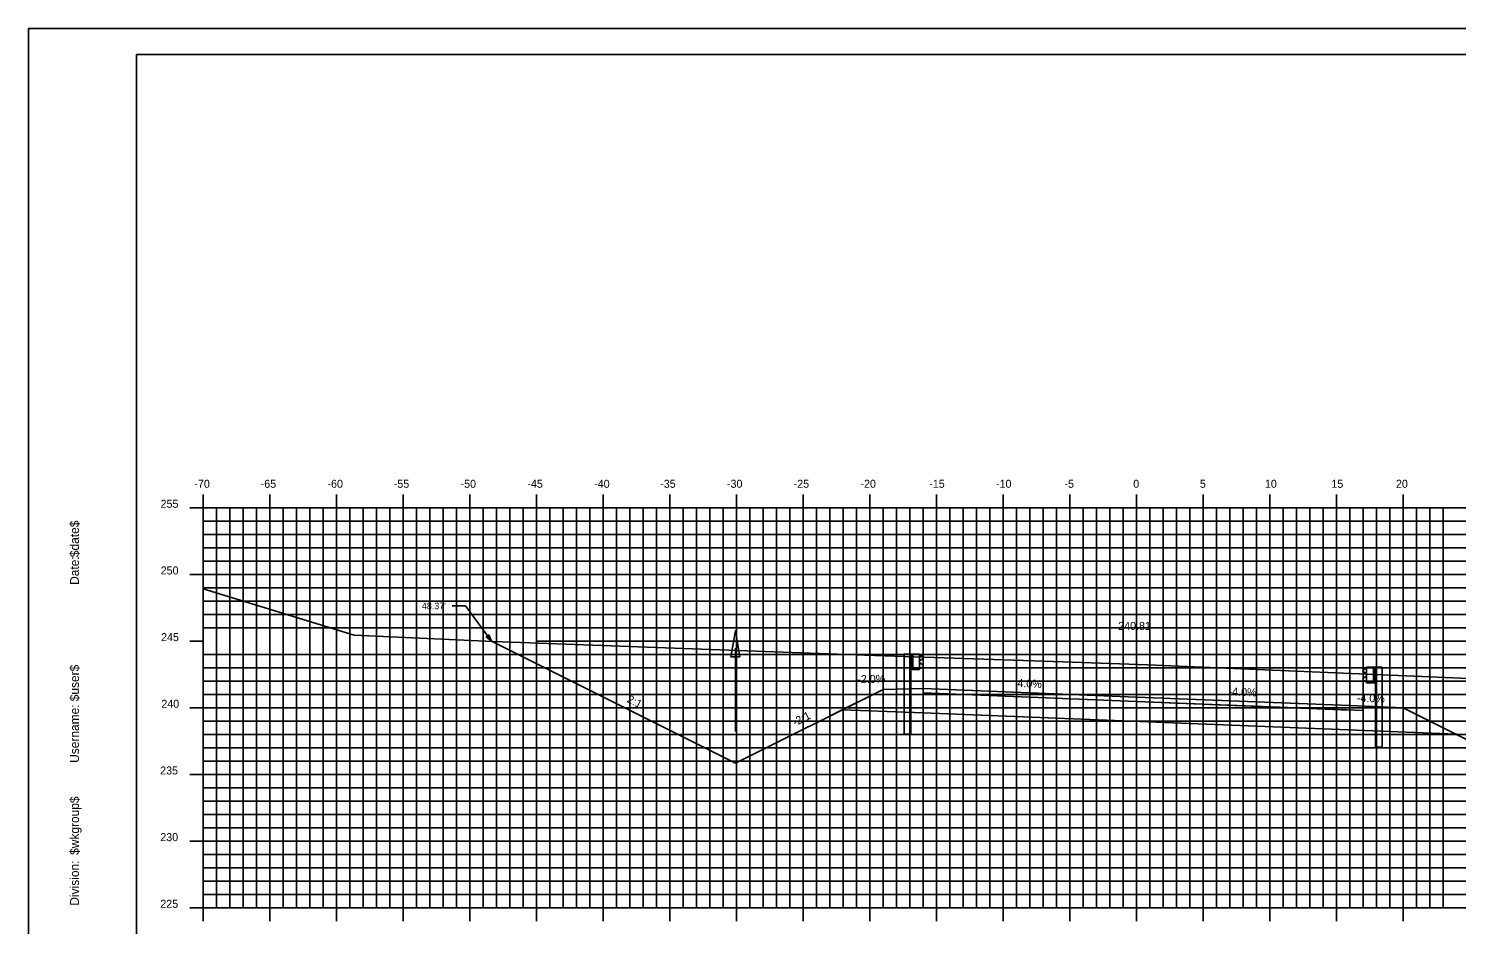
# Model space of a CAD drawing. Extents: x 1160718 to 1173142, y 616002 to 617630.
# Drawn here: x 1168548.8 to 1168655.8, y 616656.7 to 616723.9 of the extents above; entities that cross this region are included whole.
import ezdxf

# ---------------------------------------------------------------- set-up
doc = ezdxf.new("R2010")
doc.units = 0
for name, color, linetype in [('ANNOTATION', 7, 'Continuous'), ('BORDER', 7, 'Continuous'), ('D_Drainage_Ditch_Line', 7, 'Continuous'), ('D_Guardrail_Beam_Lt', 7, 'Continuous'), ('D_Guardrail_Beam_Rt', 7, 'Continuous'), ('D_Roadway_Centerline', 7, 'Continuous'), ('D_Roadway_Centerline_Text', 7, 'Continuous'), ('D_Roadway_Edge_Shoulder', 7, 'Continuous'), ('D_Roadway_Edge_TW', 7, 'Continuous'), ('D_Roadway_Pavement', 7, 'Continuous'), ('D_Roadway_SlopeLines', 7, 'Continuous'), ('D_Roadway_SubGrade', 7, 'Continuous'), ('H_V ANNOTATION', 7, 'Continuous'), ('MAJOR', 7, 'Continuous'), ('MINOR', 7, 'Continuous'), ('PLOT BOUNDARY', 7, 'Continuous'), ('S_Roadway_Centerline', 7, 'Continuous'), ('SHADING', 7, 'Continuous')]:
    doc.layers.add(name, color=color, linetype=linetype)

msp = doc.modelspace()

# ---------------------------------------------------------------- linework, layer by layer
at = {"layer": 'ANNOTATION'}
for p, q in [((1168580.52, 616680.57), (1168581.52, 616680.57)), ((1168583.49, 616677.92), (1168581.52, 616680.57)), ((1168647.85, 616673.09), (1168651.85, 616672.93))]:
    msp.add_line(p, q, dxfattribs=at)
msp.add_lwpolyline([(1168583.29, 616678.39), (1168583.49, 616677.92), (1168583.09, 616678.24)], close=True, dxfattribs=at)
at = {"layer": 'BORDER'}
for p, q in [((1168716.85, 616721.93), (1168556.85, 616721.93)), ((1168556.85, 616721.93), (1168556.85, 616616.93))]:
    msp.add_line(p, q, dxfattribs=at)
at = {"layer": 'D_Drainage_Ditch_Line'}
msp.add_line((1168601.77, 616677.39), (1168601.77, 616671.15), dxfattribs=at)
msp.add_lwpolyline([(1168602.1, 616676.74), (1168601.44, 616676.74), (1168601.77, 616678.71)], close=True, dxfattribs=at)
at = {"layer": 'D_Guardrail_Beam_Lt'}
for p, q in [((1168614.43, 616676.96), (1168614.43, 616670.96)), ((1168614.9, 616676.96), (1168614.43, 616676.96)), ((1168615.59, 616676.96), (1168614.9, 616676.96)), ((1168614.9, 616676.96), (1168614.9, 616675.79)), ((1168614.96, 616676.96), (1168614.96, 616675.79)), ((1168615.07, 616676.96), (1168615.07, 616675.79)), ((1168615.59, 616675.79), (1168615.59, 616676.96)), ((1168615.59, 616676.87), (1168615.66, 616676.86)), ((1168615.82, 616676.61), (1168615.63, 616676.47)), ((1168615.68, 616676.85), (1168615.82, 616676.75)), ((1168614.9, 616675.79), (1168615.59, 616675.79)), ((1168614.92, 616670.96), (1168614.92, 616675.79)), ((1168615.59, 616676.41), (1168615.59, 616676.34)), ((1168615.66, 616675.89), (1168615.59, 616675.87)), ((1168615.63, 616676.27), (1168615.82, 616676.14)), ((1168615.82, 616675.99), (1168615.68, 616675.89)), ((1168614.92, 616670.96), (1168614.43, 616670.96))]:
    msp.add_line(p, q, dxfattribs=at)
for centre, major_axis, start_param, end_param in [((1168615.67, 616676.41), (-0.0789, 0), 5.323254, 6.283185), ((1168615.65, 616676.82), (0.0417, 0), 0.959931, 1.376053), ((1168615.77, 616676.68), (0.0877, 0), 5.323254, 7.243116), ((1168615.67, 616676.34), (-0.0789, 0), 6.283185, 7.243116), ((1168615.65, 616675.93), (0.0417, 0), 4.907132, 5.323254), ((1168615.77, 616676.07), (0.0877, 0), 5.323254, 7.243116)]:
    msp.add_ellipse(centre, major_axis=major_axis, ratio=0.995501, start_param=start_param, end_param=end_param, dxfattribs=at)
at = {"layer": 'D_Guardrail_Beam_Rt'}
for p, q in [((1168649.02, 616675.87), (1168648.87, 616675.77)), ((1168648.87, 616675.63), (1168649.07, 616675.49)), ((1168649.11, 616675.89), (1168649.03, 616675.87)), ((1168649.1, 616675.42), (1168649.1, 616675.35)), ((1168649.11, 616675.97), (1168649.8, 616675.97)), ((1168649.11, 616674.81), (1168649.11, 616675.97)), ((1168649.63, 616675.97), (1168649.63, 616674.81)), ((1168649.73, 616675.97), (1168649.73, 616674.81)), ((1168649.8, 616675.97), (1168650.27, 616675.97)), ((1168649.8, 616675.97), (1168649.8, 616674.81)), ((1168650.27, 616675.97), (1168650.27, 616669.97)), ((1168649.07, 616675.29), (1168648.87, 616675.15)), ((1168648.87, 616675.01), (1168649.02, 616674.91)), ((1168649.03, 616674.9), (1168649.11, 616674.89)), ((1168649.8, 616674.81), (1168649.11, 616674.81)), ((1168649.77, 616669.97), (1168649.77, 616674.81)), ((1168649.77, 616669.97), (1168650.27, 616669.97))]:
    msp.add_line(p, q, dxfattribs=at)
for centre, major_axis, start_param, end_param in [((1168648.92, 616675.7), (-0.0877, 0), 5.323254, 7.243116), ((1168649.04, 616675.83), (-0.0417, 0), 4.907132, 5.323254), ((1168649.02, 616675.42), (0.0789, 0), 0, 0.959931), ((1168648.92, 616675.08), (-0.0877, 0), 5.323254, 7.243116), ((1168649.04, 616674.94), (-0.0417, 0), 0.959931, 1.376053), ((1168649.02, 616675.35), (0.0789, 0), 5.323254, 6.283185)]:
    msp.add_ellipse(centre, major_axis=major_axis, ratio=0.995501, start_param=start_param, end_param=end_param, dxfattribs=at)
at = {"layer": 'D_Roadway_Edge_Shoulder'}
msp.add_lwpolyline([(1168615.85, 616674.37), (1168615.85, 616674.04)], dxfattribs=at)
at = {"layer": 'D_Roadway_Edge_TW'}
for p, q in [((1168615.85, 616674.04), (1168615.85, 616674.37)), ((1168615.85, 616674.37), (1168631.85, 616673.73)), ((1168631.85, 616673.4), (1168615.85, 616674.04)), ((1168631.85, 616673.73), (1168647.85, 616673.09)), ((1168648.85, 616672.72), (1168631.85, 616673.4))]:
    msp.add_line(p, q, dxfattribs=at)
at = {"layer": 'D_Roadway_Pavement'}
msp.add_lwpolyline([(1168615.85, 616674.04), (1168615.85, 616674.04), (1168631.85, 616673.4), (1168647.85, 616672.76), (1168647.85, 616672.76), (1168631.85, 616673.4)], close=True, dxfattribs=at)
for points in [[(1168615.85, 616674.04), (1168615.85, 616674.04)], [(1168615.85, 616674.04), (1168615.85, 616674.04)], [(1168647.85, 616672.76), (1168647.85, 616672.76)], [(1168647.85, 616672.76), (1168647.85, 616672.76)]]:
    msp.add_lwpolyline(points, dxfattribs=at)
at = {"layer": 'D_Roadway_SlopeLines'}
for points in [[(1168601.77, 616668.77), (1168583.48, 616677.92)], [(1168612.85, 616674.31), (1168601.77, 616668.77)], [(1168651.85, 616672.93), (1168662.93, 616667.39)]]:
    msp.add_lwpolyline(points, dxfattribs=at)
at = {"layer": 'D_Roadway_SubGrade'}
for p, q in [((1168612.85, 616674.31), (1168608.87, 616672.32)), ((1168615.85, 616674.37), (1168612.85, 616674.31)), ((1168615.85, 616672.54), (1168615.85, 616674.37)), ((1168615.85, 616672.54), (1168615.85, 616674.04)), ((1168615.85, 616674.04), (1168631.85, 616673.4)), ((1168631.85, 616673.4), (1168647.85, 616672.76)), ((1168648.85, 616671.22), (1168648.85, 616673.05))]:
    msp.add_line(p, q, dxfattribs=at)
at = {"layer": 'MAJOR'}
for p, q in [((1168561.85, 616688.93), (1168561.85, 616687.93)), ((1168566.85, 616688.93), (1168566.85, 616687.93)), ((1168571.85, 616688.93), (1168571.85, 616687.93)), ((1168576.85, 616688.93), (1168576.85, 616687.93)), ((1168581.85, 616688.93), (1168581.85, 616687.93)), ((1168586.85, 616688.93), (1168586.85, 616687.93)), ((1168591.85, 616688.93), (1168591.85, 616687.93)), ((1168596.85, 616688.93), (1168596.85, 616687.93)), ((1168601.85, 616688.93), (1168601.85, 616687.93)), ((1168606.85, 616688.93), (1168606.85, 616687.93)), ((1168611.85, 616688.93), (1168611.85, 616687.93)), ((1168616.85, 616688.93), (1168616.85, 616687.93)), ((1168621.85, 616688.93), (1168621.85, 616687.93)), ((1168626.85, 616688.93), (1168626.85, 616687.93)), ((1168631.85, 616688.93), (1168631.85, 616687.93)), ((1168636.85, 616688.93), (1168636.85, 616687.93)), ((1168641.85, 616688.93), (1168641.85, 616687.93)), ((1168646.85, 616688.93), (1168646.85, 616687.93)), ((1168651.85, 616688.93), (1168651.85, 616687.93)), ((1168560.85, 616687.93), (1168561.85, 616687.93)), ((1168561.85, 616687.93), (1168701.85, 616687.93)), ((1168561.85, 616657.93), (1168561.85, 616687.93)), ((1168561.85, 616657.93), (1168561.85, 616687.93)), ((1168561.85, 616687.93), (1168701.85, 616687.93)), ((1168566.85, 616657.93), (1168566.85, 616687.93)), ((1168571.85, 616657.93), (1168571.85, 616687.93)), ((1168576.85, 616657.93), (1168576.85, 616687.93)), ((1168581.85, 616657.93), (1168581.85, 616687.93)), ((1168586.85, 616657.93), (1168586.85, 616687.93)), ((1168591.85, 616657.93), (1168591.85, 616687.93)), ((1168596.85, 616657.93), (1168596.85, 616687.93)), ((1168601.85, 616657.93), (1168601.85, 616687.93)), ((1168606.85, 616657.93), (1168606.85, 616687.93)), ((1168611.85, 616657.93), (1168611.85, 616687.93)), ((1168616.85, 616657.93), (1168616.85, 616687.93)), ((1168621.85, 616657.93), (1168621.85, 616687.93)), ((1168626.85, 616657.93), (1168626.85, 616687.93)), ((1168631.85, 616657.93), (1168631.85, 616687.93)), ((1168636.85, 616657.93), (1168636.85, 616687.93)), ((1168641.85, 616657.93), (1168641.85, 616687.93)), ((1168646.85, 616657.93), (1168646.85, 616687.93)), ((1168651.85, 616657.93), (1168651.85, 616687.93)), ((1168560.85, 616682.93), (1168561.85, 616682.93)), ((1168561.85, 616682.93), (1168701.85, 616682.93)), ((1168560.85, 616677.93), (1168561.85, 616677.93)), ((1168586.85, 616677.93), (1168701.85, 616677.93)), ((1168560.85, 616672.93), (1168561.85, 616672.93)), ((1168561.85, 616672.93), (1168701.85, 616672.93)), ((1168560.85, 616667.93), (1168561.85, 616667.93)), ((1168561.85, 616667.93), (1168701.85, 616667.93)), ((1168560.85, 616662.93), (1168561.85, 616662.93)), ((1168561.85, 616662.93), (1168701.85, 616662.93)), ((1168560.85, 616657.93), (1168561.85, 616657.93)), ((1168561.85, 616657.93), (1168701.85, 616657.93)), ((1168561.85, 616657.93), (1168701.85, 616657.93)), ((1168561.85, 616656.93), (1168561.85, 616657.93)), ((1168566.85, 616656.93), (1168566.85, 616657.93)), ((1168571.85, 616656.93), (1168571.85, 616657.93)), ((1168576.85, 616656.93), (1168576.85, 616657.93)), ((1168581.85, 616656.93), (1168581.85, 616657.93)), ((1168586.85, 616656.93), (1168586.85, 616657.93)), ((1168591.85, 616656.93), (1168591.85, 616657.93)), ((1168596.85, 616656.93), (1168596.85, 616657.93)), ((1168601.85, 616656.93), (1168601.85, 616657.93)), ((1168606.85, 616656.93), (1168606.85, 616657.93)), ((1168611.85, 616656.93), (1168611.85, 616657.93)), ((1168616.85, 616656.93), (1168616.85, 616657.93)), ((1168621.85, 616656.93), (1168621.85, 616657.93)), ((1168626.85, 616656.93), (1168626.85, 616657.93)), ((1168631.85, 616656.93), (1168631.85, 616657.93)), ((1168636.85, 616656.93), (1168636.85, 616657.93)), ((1168641.85, 616656.93), (1168641.85, 616657.93)), ((1168646.85, 616656.93), (1168646.85, 616657.93)), ((1168651.85, 616656.93), (1168651.85, 616657.93))]:
    msp.add_line(p, q, dxfattribs=at)
at = {"layer": 'MINOR'}
for p, q in [((1168562.85, 616657.93), (1168562.85, 616687.93)), ((1168563.85, 616657.93), (1168563.85, 616687.93)), ((1168564.85, 616657.93), (1168564.85, 616687.93)), ((1168565.85, 616657.93), (1168565.85, 616687.93)), ((1168567.85, 616657.93), (1168567.85, 616687.93)), ((1168568.85, 616657.93), (1168568.85, 616687.93)), ((1168569.85, 616657.93), (1168569.85, 616687.93)), ((1168570.85, 616657.93), (1168570.85, 616687.93)), ((1168572.85, 616657.93), (1168572.85, 616687.93)), ((1168573.85, 616657.93), (1168573.85, 616687.93)), ((1168574.85, 616657.93), (1168574.85, 616687.93)), ((1168575.85, 616657.93), (1168575.85, 616687.93)), ((1168577.85, 616657.93), (1168577.85, 616687.93)), ((1168578.85, 616657.93), (1168578.85, 616687.93)), ((1168579.85, 616657.93), (1168579.85, 616687.93)), ((1168580.85, 616657.93), (1168580.85, 616687.93)), ((1168582.85, 616657.93), (1168582.85, 616687.93)), ((1168583.85, 616657.93), (1168583.85, 616687.93)), ((1168584.85, 616657.93), (1168584.85, 616687.93)), ((1168585.85, 616657.93), (1168585.85, 616687.93)), ((1168587.85, 616657.93), (1168587.85, 616687.93)), ((1168588.85, 616657.93), (1168588.85, 616687.93)), ((1168589.85, 616657.93), (1168589.85, 616687.93)), ((1168590.85, 616657.93), (1168590.85, 616687.93)), ((1168592.85, 616657.93), (1168592.85, 616687.93)), ((1168593.85, 616657.93), (1168593.85, 616687.93)), ((1168594.85, 616657.93), (1168594.85, 616687.93)), ((1168595.85, 616657.93), (1168595.85, 616687.93)), ((1168597.85, 616657.93), (1168597.85, 616687.93)), ((1168598.85, 616657.93), (1168598.85, 616687.93)), ((1168599.85, 616657.93), (1168599.85, 616687.93)), ((1168600.85, 616657.93), (1168600.85, 616687.93)), ((1168602.85, 616657.93), (1168602.85, 616687.93)), ((1168603.85, 616657.93), (1168603.85, 616687.93)), ((1168604.85, 616657.93), (1168604.85, 616687.93)), ((1168605.85, 616657.93), (1168605.85, 616687.93)), ((1168607.85, 616657.93), (1168607.85, 616687.93)), ((1168608.85, 616657.93), (1168608.85, 616687.93)), ((1168609.85, 616657.93), (1168609.85, 616687.93)), ((1168610.85, 616657.93), (1168610.85, 616687.93)), ((1168612.85, 616657.93), (1168612.85, 616687.93)), ((1168613.85, 616657.93), (1168613.85, 616687.93)), ((1168614.85, 616657.93), (1168614.85, 616687.93)), ((1168615.85, 616657.93), (1168615.85, 616687.93)), ((1168617.85, 616657.93), (1168617.85, 616687.93)), ((1168618.85, 616657.93), (1168618.85, 616687.93)), ((1168619.85, 616657.93), (1168619.85, 616687.93)), ((1168620.85, 616657.93), (1168620.85, 616687.93)), ((1168622.85, 616657.93), (1168622.85, 616687.93)), ((1168623.85, 616657.93), (1168623.85, 616687.93)), ((1168624.85, 616657.93), (1168624.85, 616687.93)), ((1168625.85, 616657.93), (1168625.85, 616687.93)), ((1168627.85, 616657.93), (1168627.85, 616687.93)), ((1168628.85, 616657.93), (1168628.85, 616687.93)), ((1168629.85, 616657.93), (1168629.85, 616687.93)), ((1168630.85, 616657.93), (1168630.85, 616687.93)), ((1168632.85, 616657.93), (1168632.85, 616687.93)), ((1168633.85, 616657.93), (1168633.85, 616687.93)), ((1168634.85, 616657.93), (1168634.85, 616687.93)), ((1168635.85, 616657.93), (1168635.85, 616687.93)), ((1168637.85, 616657.93), (1168637.85, 616687.93)), ((1168638.85, 616657.93), (1168638.85, 616687.93)), ((1168639.85, 616657.93), (1168639.85, 616687.93)), ((1168640.85, 616657.93), (1168640.85, 616687.93)), ((1168642.85, 616657.93), (1168642.85, 616687.93)), ((1168643.85, 616657.93), (1168643.85, 616687.93)), ((1168644.85, 616657.93), (1168644.85, 616687.93)), ((1168645.85, 616657.93), (1168645.85, 616687.93)), ((1168647.85, 616657.93), (1168647.85, 616687.93)), ((1168648.85, 616657.93), (1168648.85, 616687.93)), ((1168649.85, 616657.93), (1168649.85, 616687.93)), ((1168650.85, 616657.93), (1168650.85, 616687.93)), ((1168652.85, 616657.93), (1168652.85, 616687.93)), ((1168653.85, 616657.93), (1168653.85, 616687.93)), ((1168654.85, 616657.93), (1168654.85, 616687.93)), ((1168561.85, 616686.93), (1168701.85, 616686.93)), ((1168561.85, 616686.93), (1168562.86, 616686.93)), ((1168561.85, 616685.93), (1168701.85, 616685.93)), ((1168561.85, 616685.93), (1168562.86, 616685.93)), ((1168561.85, 616684.93), (1168701.85, 616684.93)), ((1168561.85, 616684.93), (1168562.86, 616684.93)), ((1168561.85, 616683.93), (1168701.85, 616683.93)), ((1168561.85, 616683.93), (1168562.86, 616683.93)), ((1168561.85, 616681.93), (1168701.85, 616681.93)), ((1168561.85, 616681.93), (1168562.86, 616681.93)), ((1168561.85, 616680.93), (1168701.85, 616680.93)), ((1168561.85, 616680.93), (1168562.86, 616680.93)), ((1168561.85, 616679.93), (1168701.85, 616679.93)), ((1168561.85, 616679.93), (1168562.86, 616679.93)), ((1168561.85, 616678.93), (1168701.85, 616678.93)), ((1168561.85, 616678.93), (1168562.86, 616678.93)), ((1168561.85, 616676.93), (1168701.85, 616676.93)), ((1168561.85, 616676.93), (1168562.86, 616676.93)), ((1168561.85, 616675.93), (1168701.85, 616675.93)), ((1168561.85, 616675.93), (1168562.86, 616675.93)), ((1168561.85, 616674.93), (1168701.85, 616674.93)), ((1168561.85, 616674.93), (1168562.86, 616674.93)), ((1168561.85, 616673.93), (1168701.85, 616673.93)), ((1168561.85, 616673.93), (1168562.86, 616673.93)), ((1168561.85, 616671.93), (1168701.85, 616671.93)), ((1168561.85, 616671.93), (1168562.86, 616671.93)), ((1168561.85, 616670.93), (1168701.85, 616670.93)), ((1168561.85, 616670.93), (1168562.86, 616670.93)), ((1168561.85, 616669.93), (1168701.85, 616669.93)), ((1168561.85, 616669.93), (1168562.86, 616669.93)), ((1168561.85, 616668.93), (1168701.85, 616668.93)), ((1168561.85, 616668.93), (1168562.86, 616668.93)), ((1168561.85, 616666.93), (1168701.85, 616666.93)), ((1168561.85, 616666.93), (1168562.86, 616666.93)), ((1168561.85, 616665.93), (1168701.85, 616665.93)), ((1168561.85, 616665.93), (1168562.86, 616665.93)), ((1168561.85, 616664.93), (1168701.85, 616664.93)), ((1168561.85, 616664.93), (1168562.86, 616664.93)), ((1168561.85, 616663.93), (1168701.85, 616663.93)), ((1168561.85, 616663.93), (1168562.86, 616663.93)), ((1168561.85, 616661.93), (1168701.85, 616661.93)), ((1168561.85, 616661.93), (1168562.86, 616661.93)), ((1168561.85, 616660.93), (1168701.85, 616660.93)), ((1168561.85, 616660.93), (1168562.86, 616660.93)), ((1168561.85, 616659.93), (1168701.85, 616659.93)), ((1168561.85, 616659.93), (1168562.86, 616659.93)), ((1168561.85, 616658.93), (1168701.85, 616658.93)), ((1168561.85, 616658.93), (1168562.86, 616658.93))]:
    msp.add_line(p, q, dxfattribs=at)
at = {"layer": 'PLOT BOUNDARY'}
msp.add_lwpolyline([(1168548.76, 616613.87), (1168718.76, 616613.87), (1168718.76, 616723.87), (1168548.76, 616723.87)], close=True, dxfattribs=at)
at = {"layer": 'S_Roadway_Centerline'}
msp.add_lwpolyline([(1168561.85, 616681.86), (1168573.18, 616678.38), (1168583.61, 616677.91), (1168611.49, 616676.87), (1168626.36, 616676.38), (1168632.69, 616676.14), (1168657.95, 616675.07), (1168664.66, 616674.71), (1168680.92, 616674.74), (1168684.77, 616674.59), (1168692.8, 616672.94), (1168694.37, 616672.79), (1168701.85, 616675.05)], dxfattribs=at)
at = {"layer": 'SHADING'}
msp.add_lwpolyline([(1168609.79, 616672.78), (1168615.85, 616672.54), (1168655.84, 616670.94)], dxfattribs=at)

# ---------------------------------------------------------------- texts
at = {"layer": 'ANNOTATION'}
msp.add_text("48.37'", height=0.5, dxfattribs=at).set_placement((1168578.26, 616680.32))
for s, rotation, p in [('-2.0%', 1.1458, (1168610.92, 616674.77)), ('4.0%', 357.7094, (1168622.91, 616674.49)), ('-4.0%', 357.7094, (1168638.75, 616673.86)), ('2:1', 333.4349, (1168593.59, 616673.38)), ('-4.0%', 358.8542, (1168648.37, 616673.37)), ('-2:1', 26.5651, (1168606.24, 616671.53))]:
    msp.add_text(s, height=0.6, rotation=rotation, dxfattribs=at).set_placement(p)
at = {"layer": 'BORDER'}
for s, p in [('$date$', (1168552.54, 616684.23)), ('Date:', (1168552.54, 616682.15)), ('$user$', (1168552.54, 616673.42)), ('Username:', (1168552.54, 616668.8)), ('$wkgroup$', (1168552.54, 616661.9)), ('Division:', (1168552.54, 616658.09))]:
    msp.add_text(s, height=0.67, rotation=90, dxfattribs=at).set_placement(p)
at = {"layer": 'D_Roadway_Centerline'}
for s in ['C', 'L']:
    msp.add_text(s, height=0.0146, dxfattribs=at).set_placement((1168631.85, 616673.73))
at = {"layer": 'D_Roadway_Centerline_Text'}
msp.add_text('240.81', height=0.6, dxfattribs=at).set_placement((1168630.48, 616678.77))
at = {"layer": 'H_V ANNOTATION'}
for s, p in [('-70', (1168561.2, 616689.43)), ('-65', (1168566.17, 616689.43)), ('-60', (1168571.18, 616689.43)), ('-55', (1168576.15, 616689.43)), ('-50', (1168581.16, 616689.43)), ('-45', (1168586.17, 616689.43)), ('-40', (1168591.18, 616689.43)), ('-35', (1168596.13, 616689.43)), ('-30', (1168601.14, 616689.43)), ('-25', (1168606.14, 616689.43)), ('-20', (1168611.15, 616689.43)), ('-15', (1168616.31, 616689.43)), ('-10', (1168621.32, 616689.43)), ('-5', (1168626.45, 616689.43)), ('0', (1168631.61, 616689.43)), ('5', (1168636.61, 616689.43)), ('10', (1168641.48, 616689.43)), ('15', (1168646.47, 616689.43)), ('20', (1168651.31, 616689.43)), ('255', (1168558.66, 616687.93)), ('250', (1168558.67, 616682.93)), ('245', (1168558.7, 616677.93)), ('240', (1168558.72, 616672.93)), ('235', (1168558.63, 616667.93)), ('230', (1168558.64, 616662.93)), ('225', (1168558.64, 616657.93))]:
    msp.add_text(s, height=0.6, dxfattribs=at).set_placement(p)

doc.saveas('drawing.dxf')
